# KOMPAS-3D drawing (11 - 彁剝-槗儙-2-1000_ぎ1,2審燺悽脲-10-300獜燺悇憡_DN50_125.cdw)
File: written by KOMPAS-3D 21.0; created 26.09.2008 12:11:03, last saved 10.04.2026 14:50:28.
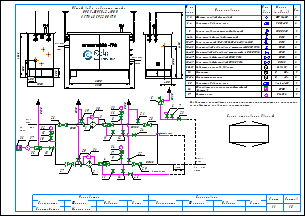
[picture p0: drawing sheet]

Sheets 1-2: A3, landscape

Document properties: Наименование: Макро:21; Автор: RaskoAdmin; Форматы листов документа: 2xA3; Полное имя файла: \\UR38nt01\Departments\КТО\КБ ПУРДГ\Заявки\Прайс-лист на типовые шкафы ГРПШ\ПРДГ_стандарт_20_03_2026\ПРДГ с РДСК\ПРДГ-ШУГО-2-1000_до1,2МПа_Рвых-10-300кПа_РДСК_DN50_125.cdw

Title block, sheet 1: Наименование: Пункт учета газа / ПУГ-Ш-400-Р / ЛГТИ.485922.001ТУ; designation: ЛГТИ.03.4411141; sheet number: 1; Количество листов документа: 2; organisation: ООО "ЭЛЬСТЕР Газэлектроника"; Форматы листов документа: A3; stored path: C:\Рабочие документы\Компас\ПУГ\Схема.cdw; Разработал: Устинов; Проверил: Кошкин; Утвердил: Кошкин
Title block, sheet 2: sheet number: 2; stored path: D:\Рабочие документы\Заявки\ПУРДГ\ПУРДГ-ШУЭО-2-100-Р 4411220.cdw; designation, second copy: ЛГТИ.03.4411141-

Views: Вид 1, Вид 2
Referenced files: wcvoit.frw
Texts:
  Normal
  Вход
  газа
  PDI
  Выход
  Р=     кПа
  DN125
  DN50
  DN20
  Импульс DN20
  ≥5DN
  HYSWLongFangSong
  № на
  схеме
  Усл.
  обозн.
  Марка
  (модель)
  Кол.
  Фильтр газовый фланцевый
  ФГ 16-50
  Регулятор давления газа
  РДCК-50
  Клапан предохранительный сбросной
  КПС DN20
  Кран шаровой газовый латунный
  DN15
  Кран кнопочный VE-РАСКО-НЗ-1,6-G1/2-М20
  Кран шаровой "под приварку" штуцерный DN20 PN16
  Кран шаровой "под приварку" штуцерный п/п DN20 PN16
  Кран шаровой фланцевый DN50 PN16
  Кран шаровой фланцевый DN125 PN16
  Индикатор перепада давления
  Delta 15
  Манометр
  Манометр-напоромер
  0...     МПа
  0...     кПа
  Обогреватель газогорелочный шкафной
  (Эльтон")
  Счетчик газа
  Venio-A-15
  ОГШН
  BK-G1,6
  Общий вид и габариты шкафа
  ПРДГ-ШУГО-2-1000
  Выход газа
  Вход газа
  Схема открывания дверей
  Р=        МПа
  logo-rasko-ge.png
  Предприятие изготовитель может заменять комплектующие на аналогичные,
  не ухудшающие заявленных характеристик.
  Должность
  Конструктор
  Фамилия
  Подпись
  Дата
  Согласовано
  Максимкин
  Лист
  Листов
  POLYLINE_STYLE_0.18_RGB_0_0_0
  POLYLINE_STYLE_0.50_RGB_0_0_0
  POLYLINE_STYLE_0.34_RGB_0_0_0
  PHANTOM_RGB_0_0_0_SC_1_THICK_0.18
  K5LT_THIN_RGB_0_0_0_THICK_0.18
  K5LT32769_RGB_0_0_0_THICK_0.18
  K5LT12_RGB_0_0_0_SC_1_THICK_0.18
  K5LT_DASHED_RGB_0_0_0_SC_1_THICK_0.18
  ACISOTGL_RGB_0_0_0_SC_0.8_THICK_0.25
  CONTINUOUS_RGB_0_127_31_THICK_0.3
  CONTINUOUS_RGB_0_0_255_THICK_0.35
  CONTINUOUS_RGB_255_0_0_THICK_0.35
  POLYLINE_STYLE_0.25_RGB_0_0_0
  CONTINUOUS_RGB_0_0_0_THICK_0.5
  POLYLINE_STYLE_0.35_RGB_0_0_255
  CONTINUOUS_RGB_0_0_0_THICK_0.4
  CONTINUOUS_RGB_0_0_0_THICK_0.35
  Без оформления
Dimensions and other numbers on the sheet: 1; 2; 3; 4; 5; 10; 27; 28; 29; 23; 8; 12; 18; 19; 20; 21; 22; 25; 24; 30; 31; 15; 16; 35; 36; 26; 6; 7; 11; 14; 13; 33; 1, 2; 3, 4; 6-14; 9; 15-17; 18-23; 24-25; 26-27; 28-29; 30-31; 32; 33-34; 37; 400; 1050; 500; 305; 2500; 1565; 2800; 17; 34; 1000; 4130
